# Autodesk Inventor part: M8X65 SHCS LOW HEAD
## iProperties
Created: 2006-02
Part Number: M8X65 SHCS LOW HEAD
Material: Steel, Mild
Description: Cylinder Head Cap Screw
Document SubType Name: Modeling
Standard: DIN 7984
Designer: Andy Moles
Standards Organization: DIN
Language: en-US
Size Designation: M8 x 60
Categories: <MemberInstance><Categories><Category DisplayName="Fasteners" InternalName="e4da775c-781d-43d5-af7c-5136215cf5a6" Mnemonic="FSTN"><Category DisplayName="Bolts"
Density: 7.86 g/cm^3
Mass: 30.0419 g
Surface Area: 21.4864 cm^2
Volume: 3.82213 cm^3
Author: Andy Moles
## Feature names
1. Body [Revolution]
2. Slot [Extrusion]
3. Fillet1
4. Chamfer1
